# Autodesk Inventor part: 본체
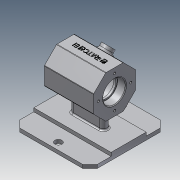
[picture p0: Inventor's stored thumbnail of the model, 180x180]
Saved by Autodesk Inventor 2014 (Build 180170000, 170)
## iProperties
Created: 2018-06
Part Number: 본체
Material: 알루미늄 6061
Document SubType Name: Modeling
Designer: NET
Density: 2.71 g/cm^3
Appearance: 알루미늄 - 평지
Mass: 554.044 g
Surface Area: 601.885 cm^2
Volume: 204.444 cm^3
Author: NET
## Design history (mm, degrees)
sketch "스케치1"
  geometry: L1 (-55, -55)-(55, -55); L2 (55, -55)-(55, 55); L3 (55, 55)-(-55, 55); L4 (-55, 55)-(-55, -55); L5 (-55, -55)-(55, 55); L6 (55, -55)-(-55, 55); 1 further point
  constraints: 12 end point, 2 midpoint, 2 parallel, 2 perpendicular, 1 horizontal
  dimensions: "d0" = 110 distance of L2.end L3.end
extrude "돌출1" new body sketch "스케치1" distance "d1" = 5; taper "d2" = 0 deg
sketch "스케치2"
  geometry: L1 (55, -55)-(55, 55) reference; L2 (55, 55)-(-55, 55) reference; L3 (-55, -25)-(55, -25); L4 (55, -25)-(55, 25); L5 (55, 25)-(-55, 25); L6 (-55, 25)-(-55, -25); L7 (-55, -25)-(55, 25); L8 (55, -25)-(-55, 25); 1 further point
  constraints: 12 end point, 2 midpoint, 2 parallel, 1 horizontal, 1 perpendicular, 1 point on line
  dimensions: "d3" = 30 distance between parallel lines of L2 L5
extrude "돌출2" join sketch "스케치2" distance "d4" = 5; taper "d5" = 0 deg
sketch "스케치3" dims "d6" = 60
  geometry: L1 (12.426, 92)-(30, 74.426); L2 (30, 74.426)-(30, 49.574); L3 (30, 49.574)-(12.426, 32); L4 (12.426, 32)-(-12.426, 32); L5 (-12.426, 32)-(-30, 49.574); L6 (-30, 49.574)-(-30, 74.426); L7 (-30, 74.426)-(-12.426, 92); L8 (-12.426, 92)-(12.426, 92); 4 further points
  constraints: 16 end point, 3 vertical alignment, 1 coincident, 1 midpoint, 19 other
  dimensions: "d7" = 62 distance of point (0, 0) point (0, 62)
extrude "돌출3" join sketch "스케치3" stored distance "d8" = 70; taper "d9" = 0 deg
sketch "스케치4"
  geometry: L1 (55, 25)-(-55, 25) reference; L2 (-19, 0)-(19, 0); L3 (-19, -5)-(19, -5); L4 (19, 5)-(-19, 5); A1 r 5 centre (-19, 0) between (-19, 5) and (-19, -5); A2 r 5 centre (19, 0) between (19, -5) and (19, 5); 1 further point
  constraints: 8 end point, 4 point on circle, 4 tangent, 2 centre point, 2 parallel, 1 horizontal alignment, 1 midpoint
  dimensions: "d10" = 5 radius of A2; "d11" = 38 distance of L2.start L2.end
extrude "돌출4" join sketch "스케치4" stored distance "d12" = 70; taper "d13" = 0 deg
sketch "스케치5"
  geometry: L1 (12.426, 92)-(30, 74.426) reference; L2 (30, 74.426)-(30, 49.574) reference; L3 (30, 49.574)-(12.426, 32) reference; L4 (12.426, 32)-(-12.426, 32) reference; L5 (-12.426, 32)-(-30, 49.574) reference; L6 (-30, 49.574)-(-30, 74.426) reference; L7 (-30, 74.426)-(-12.426, 92) reference; L8 (-12.426, 92)-(12.426, 92) reference; L9 (0, 62)-(26.163, 88.163); L10 (0, 62)-(30, 62); 2 further points
  constraints: 4 end point, 2 midpoint, 1 horizontal alignment, 1 perpendicular, 1 vertical alignment
  dimensions: "d14" = 45 deg angle of L9 L10; "d15" = 7 distance from line of L9.end L1
  node "투영된 루프1"
node "작업 평면1"
sketch "스케치6"
  geometry: C1 r 8 at (0, 0); 4 further points
  constraints: 1 centre point, 1 coincident
  dimensions: "d16" = 16 diameter of C1
extrude "돌출5" join sketch "스케치6" stored distance "d17" = 70; taper "d18" = 0 deg
sketch "스케치7"
  geometry: L1 (-35, 74.426)-(-35, 49.574) reference; L2 (-35, 92)-(-35, 74.426) reference; L3 (-35, 49.574)-(-35, 32) reference; L4 (35, 74.426)-(35, 92) reference; L5 (35, 49.574)-(35, 74.426) reference; L6 (35, 32)-(35, 49.574) reference; L7 (-52.18, 62)-(53.63, 62); L8 (55, 0)-(-55, 0) reference; L9 (-35, 78)-(-23.3, 78); L10 (-23, 77.7)-(-23, 76); L11 (-23, 76)-(-20, 76); L12 (-20, 76)-(-20, 84); L13 (-17, 87)-(17, 87); L14 (20, 84)-(20, 76); L15 (20, 76)-(23, 76); L16 (23, 76)-(23, 77.7); L17 (23.3, 78)-(35, 78); L18 (-35, 78)-(-35, 62); L19 (35, 78)-(35, 62); L20 (35, 62)-(-35, 62); A1 r 0.3 centre (-23.3, 77.7) between (-23, 77.7) and (-23.3, 78); A2 r 0.3 centre (23.3, 77.7) between (23.3, 78) and (23, 77.7); A3 r 3 centre (17, 84) between (20, 84) and (17, 87); A4 r 3 centre (-17, 84) between (-17, 87) and (-20, 84); 4 further points
  constraints: 26 end point, 10 point on line, 8 point on circle, 8 tangent, 7 parallel, 5 collinear, 4 centre point, 3 perpendicular, 2 equal radius, 2 midpoint
  dimensions: "d19" = 62 distance between parallel lines of L8 L7; "d20" = 40 distance of point (-20, 87) point (20, 87); "d21" = 12 distance of point (23, 78) L17.end; "d22" = 50 diameter of L13 L7; "d23" = 32 diameter of L9 L7; "d24" = 28 diameter of L11 L7; "d25" = 0.3 radius of A1; "d26" = 3 radius of A3
revolve "회전1" sketch "스케치7" stored, may be unused: angle "d27" = 90 deg
chamfer "모따기1" distance "d28" = 1; stored, may be unused: second distance "d29" = 2, angle "d30" = 45 deg
sketch "스케치8"
  geometry: C1 r 17 at (-62, 0) reference; 2 further points
  constraints: 1 vertical alignment
  dimensions: "d31" = 23 distance of C1.centre point (-62, 23)
hole "구멍1" sketch "스케치8" at (-62, 23) diameter "d32" = 3.242; stored, may be unused: countersink angle "d36" = 90 deg, drill point angle "d38" = 118 deg; dims "d33" = 8, "d34" = 4, "d35" = 2, "d37" = 10
sketch "스케치9"
  geometry: C1 r 8 at (0, 0) reference; C2 r 4 at (0, 0); 1 further point
  constraints: 1 centre point, 1 coincident
  dimensions: "d42" = 8 diameter of C2
extrude "돌출6" cut sketch "스케치9" distance "d43" = 27.5; taper "d44" = 0 deg
chamfer "모따기2" distance "d45" = 1; stored, may be unused: second distance "d46" = 2, angle "d47" = 45 deg
sketch "스케치10"
  geometry: L1 (0, 24.853)-(0, 42.426) reference; L2 (70, 42.426)-(0, 42.426) reference; 2 further points
  constraints: 1 other
  dimensions: "d48" = 35 distance from line of L1 point (35, 12.426); "d49" = 30 distance from line of point (35, 12.426) L2
feature "엠보싱1" sketch "스케치10" dims "d0" = 110, "d6" = 60, "d7" = 62, "d50" = 0.5, "d51" = 0
sketch "스케치11"
  geometry: L1 (55, 55)-(-55, 55) reference; C1 r 5 at (0, 45); 1 further point
  constraints: 1 centre point
  dimensions: "d52" = 10 diameter of C1; "d53" = 10 distance from line of L1 C1.centre
extrude "돌출7" cut sketch "스케치11" distance "d54" = 27.5; taper "d55" = 0 deg
fillet "모깎기1" dims "d56" = 2
fillet "모깎기2" dims "d57" = 1
fillet "모깎기3" dims "d58" = 1
chamfer "모따기3" distance "d59" = 10; stored, may be unused: second distance "d60" = 2, angle "d61" = 45 deg
fillet "모깎기4" dims "d62" = 3
node "솔리드1"
pattern_circular "원형 패턴1" dims angle "d40" = 360 deg
mirror "대칭1"
mirror "대칭2"
